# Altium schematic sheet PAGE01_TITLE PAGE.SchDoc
size 246 x 182 mm
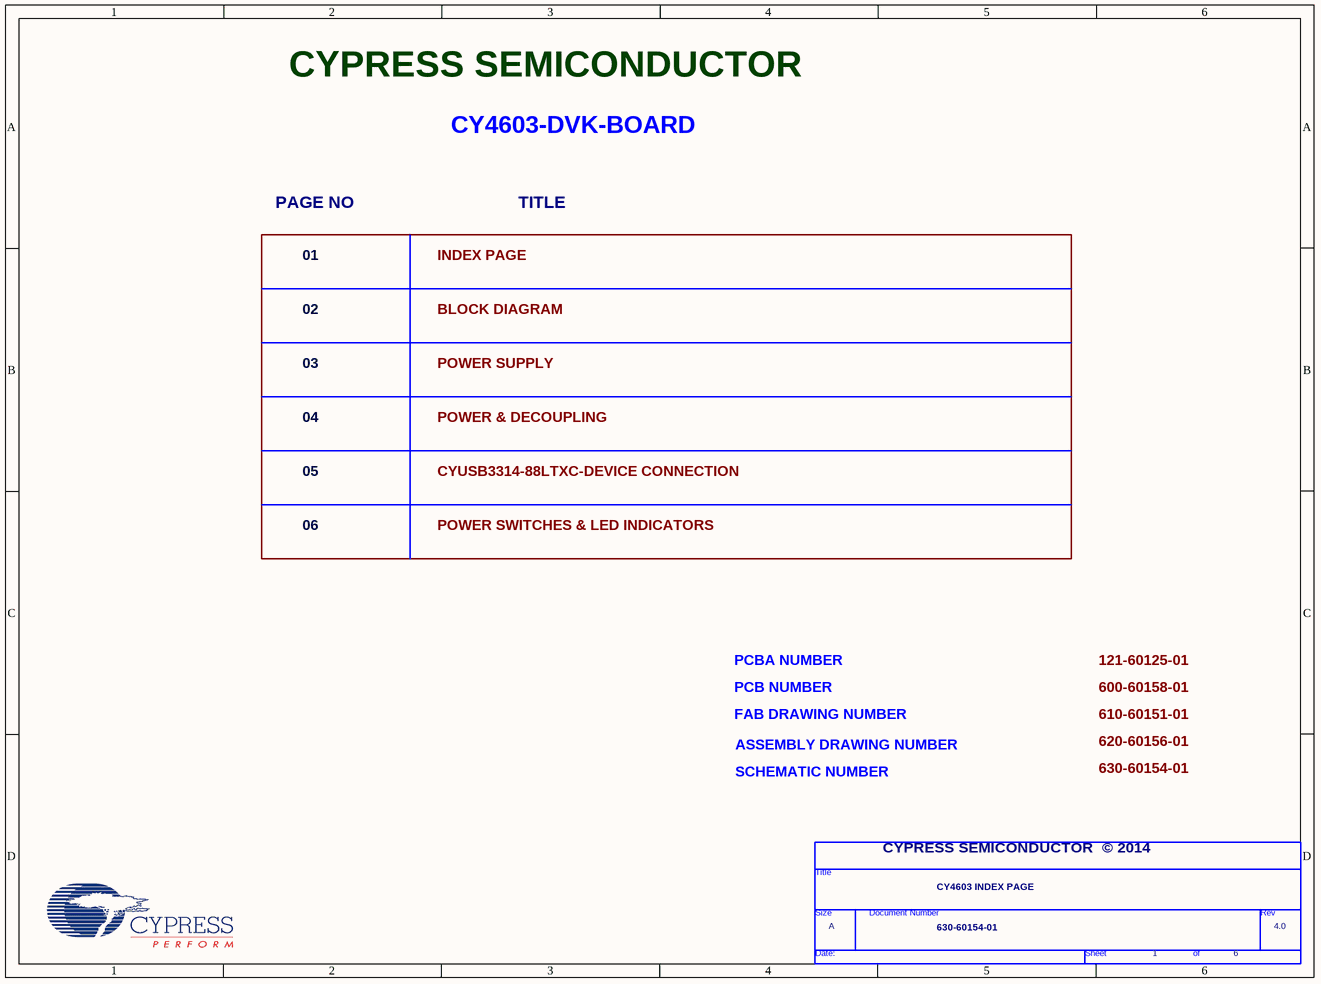
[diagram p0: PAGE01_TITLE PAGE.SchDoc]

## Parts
*  Page Count: 6  Page Number: 1  Page Size: A  Title: CY4603 INDEX PAGE  RevCode: 4.0  Doc: 630-60154-01  (hidden comment: TitleBlock0)  (graphical)

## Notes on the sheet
- CYPRESS SEMICONDUCTOR
- CY4603-DVK-BOARD
- PAGE NO
- 01
- INDEX PAGE
- TITLE
- 02
- BLOCK DIAGRAM
- 03
- POWER SUPPLY
- 04
- POWER & DECOUPLING
- 05
- 06
- CYUSB3314-88LTXC-DEVICE CONNECTION
- POWER SWITCHES & LED INDICATORS
- PCBA NUMBER
- 121-60125-01
- PCB NUMBER
- FAB DRAWING NUMBER
- 600-60158-01
- 610-60151-01
- ASSEMBLY DRAWING NUMBER
- SCHEMATIC NUMBER
- 620-60156-01
- 630-60154-01
- CYPRESS SEMICONDUCTOR  © 2014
